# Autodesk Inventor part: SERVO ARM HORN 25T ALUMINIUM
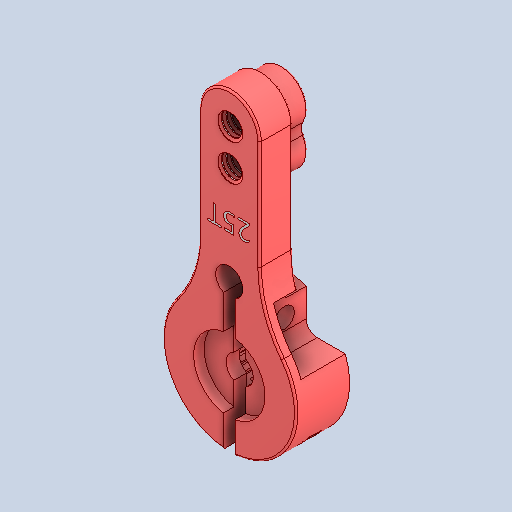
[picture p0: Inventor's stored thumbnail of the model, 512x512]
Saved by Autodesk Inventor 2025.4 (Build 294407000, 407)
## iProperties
Created: 2026-09
Part Number: SERVO ARM HORN 25T ALUMINIUM
Material: Generic
Description: STEP AP214
Document SubType Name: Modeling
Designer: AdminForWorker
Density: 1 g/cm^3
Appearance: Default
Title: SERVO ARM HORN 25T ALUMINIUM v1
Author: AdminForWorker
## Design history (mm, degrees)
feature "Body1"
body "Solid1"
